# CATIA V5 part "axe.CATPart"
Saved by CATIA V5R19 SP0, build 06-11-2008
Part number: axe
Bounding box of the stored display mesh (mm): x 0 to 40.1, y -11 to 11, z -11 to 11
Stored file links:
  I:\mediator\axe.CATPart
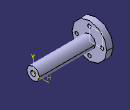
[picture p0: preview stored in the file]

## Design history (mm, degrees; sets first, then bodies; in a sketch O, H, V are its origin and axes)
Body1 (main body)
  Sketch1 on yz-plane, origin (0, 0, 0), H (0, 1, 0), V (0, 0, 1)
    circle A1 centre (0, 0) radius 4
    radius A1 = 4
  Pad1: profile Sketch1, direction (1, 0, 0), length 40.1
  Plane1: type Offset, Offset 0.7, RefPlane yz-plane
  Sketch2 on Plane1, origin (0.7, 0, 0), H (0, 1, 0), V (0, 0, 1)
    circle A1 centre (0, 0) radius 11
    radius A1 = 11
  Pad2: profile Sketch2, direction (1, 0, 0), length 4
  Sketch3 on start face of Pad2, origin (0.7, 0, 0), H (0, -1, 0), V (0, 0, 1)
    circle A1 centre (0, 8) radius 1.1
    point P1 (0, 8)
    axis line L1 (-9.1, 0) -> (6.9, 0)
    point P2 (-9.1, 0)
    point P3 (6.9, 0)
    circle A2 centre (0, -8) radius 1.1
    circle A3 centre (8, 0) radius 1.1
    point P5 (8, 0)
    circle A4 centre (-8, 0) radius 1.1
    point P6 (-8, 0)
    distance P1 A1 = 1.1
    radius A3 = 1.1
    radius A4 = 1.1
    coincidence: P1 V, P5 H, A3 P3, P6 L1, A4 P2
    horizontal: L1 H
    symmetry: A1 A2 L1
  Pocket1: profile Sketch3, direction (1, 0, 0), length 4
  Sketch4 on start face of Pad1, origin (0, 0, 0), H (0, -1, 0), V (0, 0, 1)
    circle A1 centre (0, 0) radius 2.8
    radius A1 = 2.8
  Pocket2: profile Sketch4, direction (1, 0, 0), length 0.7
  Sketch5 on end face of Pocket2, origin (0.7, 0, 0), H (0, -1, 0), V (0, 0, 1)
    circle A1 centre (0, 0) radius 1.4
    radius A1 = 1.4
  Pocket3: profile Sketch5, direction (1, 0, 0), length 5
  Sketch6 on end face of Pad1, origin (40.1, 0, 0), H (0, 1, 0), V (0, 0, 1)
    reference projected circle E1 centre (0, 0) radius 4 from edge [face of Pad1 from Sketch1.A1 | end face of Pad1]
    radius E1 = 4 (reference)
  Sketch7 on end face of Pad1, origin (40.1, 0, 0), H (0, 1, 0), V (0, 0, 1)
    circle A1 centre (0, 0) radius 1.6
    radius A1 = 1.6
  Pocket4: profile Sketch7, direction (-1, 0, 0), length 1.5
